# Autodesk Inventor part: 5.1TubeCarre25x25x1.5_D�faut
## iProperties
Created: 2011-01
Part Number: 5.1TubeCarre25x25x1.5_D�faut
Document SubType Name: Modeling
Designer: eric
Density: 1 g/cm^3
Mass: 10.5809 g
Surface Area: 144.724 cm^2
Volume: 10.5809 cm^3
Author: eric
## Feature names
1. Base1
